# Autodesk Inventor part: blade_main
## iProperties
Shininess: 86.0
Length Units: 11269
Angle Units: 11279
Time Units: 11290
Mass Units: 11283
Length Display Precision: 3
Angle Display Precision: 2
Compacted: True
Manager: Lebovitz
Company: Autodesk
Created: 2000-05
Part Number: blade_main
Document SubType Name: Modeling
Designer: The PD Team
Project: Inventor Samples
Density: 1 g/cm^3
Density: 0.0
Volumn: 0.0
Area: 0.0
PropertySet Name: Model Information
Control State: 0
Master: False
Checked Out: False
Author: The PD Team
Revision Number: A
